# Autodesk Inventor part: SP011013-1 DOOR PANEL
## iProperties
Created: 2013-01
Part Number: SP011013-1 DOOR PANEL
Material: Polycarbonate, Clear
Document SubType Name: Modeling
Designer: Administrator
Mass: 2467.97 g
Surface Area: 7559.91 cm^2
Volume: 2056.64 cm^3
Density: 1.2 g/cm^3
Author: Administrator
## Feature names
1. Extrusion1
2. Extrusion2
3. Mirror1
